(* Logix 5000 project; controller MVI69ADMNET vendor 1 type 14 code 65 rev 13.1; software revision 13.00 *)
// Sample Ladder for MVI69-ADMNET

TASK MainTask (continuous, watchdog 500 ms) : MainProgram

MODULES
   Controller : vendor 1 type 14 code 65 (CompactLogixL35Controller 0, rev 13.1)
      LocalENB : 1769-L35E Ethernet Port (CompactLogixL35Ethernet 1, Ethernet 192.168.0.149, rev 13.1)
      Local : CompactBus (CompactVirtualAdapter 3, rev 13.1, Output RPI 2 ms)
         MVI69 : 1769-MODULE (Compact 1, rev 1.1, Output RPI 2 ms)
END_MODULES

TYPE ADMModuleDef :
STRUCT
   ReadData : INT[600];
   WriteData : INT[600];
END_STRUCT
END_TYPE

VAR_GLOBAL   (* controller tags *)
   ADMNET : ADMModuleDef;
END_VAR

PROGRAM MainProgram   (* routine attr 65 MainRoutine *)
VAR
   MCM : DINT;
END_VAR

ROUTINE MainRoutine   (* ladder *)
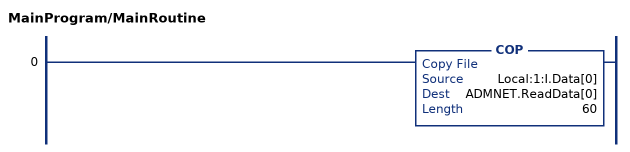
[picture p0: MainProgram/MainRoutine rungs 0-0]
   0: COP(Local:1:I.Data[0],ADMNET.ReadData[0],60);
END_ROUTINE
END_PROGRAM
